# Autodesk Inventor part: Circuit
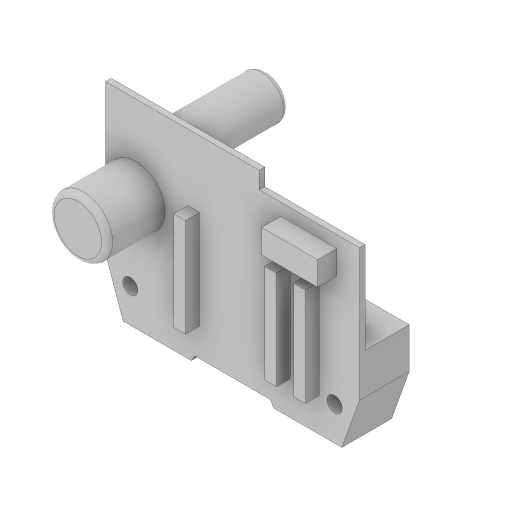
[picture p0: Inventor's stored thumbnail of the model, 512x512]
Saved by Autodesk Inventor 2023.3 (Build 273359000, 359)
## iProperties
Created: 2017-10
Part Number: Circuit
Material: Générique
Document SubType Name: Modeling
Designer: peter.letaif
Density: 1 g/cm^3
Appearance: Par défaut
Author: peter.letaif
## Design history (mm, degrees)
sketch "Sketch1"
  geometry: L1 (-35.832, 37.865)-(19.808, 37.865); L2 (19.808, 37.865)-(19.808, 31.705); L3 (19.808, 31.705)-(56.168, 31.705); L4 (56.168, 31.705)-(56.168, -16.095); L5 (56.168, -16.095)-(49.758, -34.135); L6 (49.758, -34.135)-(25.106, -34.135); L7 (-35.832, 37.865)-(-35.832, -16.095); L8 (-35.832, -16.095)-(-29.422, -34.135); L9 (-29.422, -34.135)-(-4.762, -34.135); L10 (-4.762, -34.135)-(-3.508, -32.045); L11 (-3.508, -32.045)-(23.852, -32.045); L12 (23.852, -32.045)-(25.106, -34.135); 1 further point
  constraints: 24 end point, 3 horizontal, 3 perpendicular, 1 parallel, 1 vertical
  dimensions: "d0" = 55.64 distance of L1.start L1.end; "d1" = 36.36 distance of L2.end L3.end; "d2" = 6.16 distance of L1.end L2.end; "d3" = 47.8 distance of L3.end L4.end; "d4" = 18.04 vertical distance of L4.end L5.end; "d5" = 6.41 horizontal distance of L5.end L4.end; "d6" = 6.41 horizontal distance of L8.end L7.end; "d7" = 18.04 vertical distance of L7.end L8.end; "d8" = 53.96 distance of L1.start L7.end; "d9" = 24.66 distance of L8.end L9.end; "d10" = 120.96 deg angle of L9 L10; "d11" = 2.09 distance between parallel lines of L9 L11; "d12" = 27.36 distance of L10.end L11.end; "d13" = 120.96 deg angle of L6 L12
extrude "Extrusion1" new body sketch "Sketch1" distance "d14" = 2; taper "d15" = 0 deg
sketch "Sketch2"
  geometry: L1 (19.808, 37.865)-(-35.832, 37.865) reference; L2 (-35.832, 37.865)-(-35.832, -16.095) reference; C1 r 10.595 at (-24.842, 7.665); 1 further point
  constraints: 1 centre point
  dimensions: "d16" = 21.19 diameter of C1; "d17" = 30.2 distance from line of L1 C1.centre; "d18" = 10.99 distance from line of L2 C1.centre
extrude "Extrusion2" join sketch "Sketch2" distance "d19" = 21; taper "d20" = 0 deg
fillet "Fillet1" dims "d21" = 2
sketch "Sketch3"
  geometry: L1 (27.748, 27.365)-(47.928, 27.365); L2 (47.928, 27.365)-(47.928, 18.735); L3 (47.928, 18.735)-(27.748, 18.735); L4 (27.748, 18.735)-(27.748, 27.365); L5 (56.168, 31.705)-(19.808, 31.705) reference; L6 (56.168, -16.095)-(56.168, 31.705) reference; 1 further point
  constraints: 8 end point, 2 parallel, 1 horizontal, 1 perpendicular
  dimensions: "d22" = 20.18 distance of L1.start L1.end; "d23" = 8.63 distance of L1.end L2.end; "d24" = 4.34 distance between parallel lines of L5 L1; "d25" = 8.24 distance between parallel lines of L6 L2
extrude "Extrusion3" join sketch "Sketch3" distance "d26" = 7; taper "d27" = 0 deg
sketch "Sketch4"
  geometry: L1 (41.558, 13.755)-(37.338, 13.755); L2 (37.338, 13.755)-(37.338, -21.925); L3 (37.338, -21.925)-(41.558, -21.925); L4 (41.558, -21.925)-(41.558, 13.755); L5 (25.106, -34.135)-(49.758, -34.135) reference; L6 (56.168, -16.095)-(56.168, 31.705) reference; 1 further point
  constraints: 8 end point, 2 parallel, 1 horizontal, 1 perpendicular
  dimensions: "d28" = 4.22 distance of L1.start L1.end; "d29" = 35.68 distance of L3.end L1.start; "d30" = 12.21 distance between parallel lines of L5 L3; "d31" = 14.61 distance between parallel lines of L6 L4
extrude "Extrusion4" join sketch "Sketch4" distance "d32" = 5; taper "d33" = 0 deg
pattern_linear "Rectangular Pattern1" dims "d36" = 10.47
pattern_linear "Rectangular Pattern2" dims "d39" = 43.41
sketch "Sketch5"
  geometry: L1 (35.832, -16.095)-(35.832, 37.865) reference; L2 (35.832, 37.865)-(-19.808, 37.865) reference; C1 r 7.88 at (15.232, 25.175); 1 further point
  constraints: 1 centre point
  dimensions: "d59" = 15.76 diameter of C1; "d61" = 20.6 distance from line of L1 C1.centre; "d62" = 12.69 distance from line of L2 C1.centre
extrude "Extrusion5" join sketch "Sketch5" distance "d63" = 36; taper "d64" = 0 deg
fillet "Fillet2" dims "d65" = 2
sketch "Sketch6"
  geometry: L1 (-56.168, 31.705)-(-56.168, -16.095) reference; L2 (-56.168, -1.445)-(-56.168, -16.095); L3 (-56.168, -16.095)-(-49.758, -34.135) reference; L4 (-56.168, -16.095)-(-49.758, -34.135); L5 (-25.106, -34.135)-(-49.758, -34.135) reference; L6 (-49.758, -34.135)-(-25.106, -34.135); L7 (-25.106, -34.135)-(-23.852, -32.045) reference; L8 (-25.106, -34.135)-(-23.852, -32.045); L9 (3.508, -32.045)-(-23.852, -32.045) reference; L10 (-23.852, -32.045)-(3.508, -32.045); L11 (4.762, -34.135)-(3.508, -32.045) reference; L12 (3.508, -32.045)-(4.762, -34.135); L13 (29.422, -34.135)-(4.762, -34.135) reference; L14 (4.762, -34.135)-(29.422, -34.135); L15 (35.832, -16.095)-(29.422, -34.135) reference; L16 (29.422, -34.135)-(35.832, -16.095); L17 (35.832, -16.095)-(35.832, -1.445); L18 (35.832, 37.865)-(35.832, -16.095) reference; L19 (-56.168, -1.445)-(35.832, -1.445); 1 further point
  constraints: 20 end point, 6 collinear, 2 point on line, 1 parallel, 1 perpendicular, 1 vertical
  dimensions: "d66" = 32.69 distance between parallel lines of L5 L19
extrude "Extrusion6" join sketch "Sketch6" distance "d67" = 16; taper "d68" = 0 deg
sketch "Esquisse8"
  geometry: L1 (-29.422, -34.135)-(-4.762, -34.135) reference; 1 further point
  dimensions: "d69" = 12.31 distance from line of L1 point (-26.832, -21.825)
hole "Hole3" sketch "Esquisse8" at (-26.832, -21.825) diameter "d71" = 5.5; stored, may be unused: countersink angle "d75" = 90 deg, drill point angle "d77" = 0 deg; dims "d72" = 6, "d73" = 4, "d74" = 2, "d76" = 8
sketch "Esquisse7"
  geometry: L1 (25.106, -34.135)-(49.758, -34.135) reference; 1 further point
  dimensions: "d78" = 12.31 distance from line of L1 point (47.168, -21.825)
hole "Hole4" sketch "Esquisse7" at (47.168, -21.825) diameter "d80" = 5.5; stored, may be unused: countersink angle "d84" = 90 deg, drill point angle "d86" = 0 deg; dims "d81" = 6, "d82" = 4, "d83" = 2, "d85" = 8
body "Solid1"
other parameters: "d70" = 1, "d79" = 1
